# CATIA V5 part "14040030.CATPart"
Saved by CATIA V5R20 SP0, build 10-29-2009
Part number: 14040030
Definition: NONE
Nomenclature: 14040030
Source: Unknown
Description: 14040030
Bounding box of the stored display mesh (mm): x -15 to 60, y -34 to 23.924, z -24.1 to 24.1
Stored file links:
  C:\Users\Utente\Desktop\IO LAVORO\3D X SITO CF\X SITO\PLASTICA\RF2\14040030.CATPart
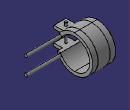
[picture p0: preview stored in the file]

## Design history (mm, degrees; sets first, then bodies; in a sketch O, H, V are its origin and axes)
Body1 "14040030" (main body)
  Solid1: solid without history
